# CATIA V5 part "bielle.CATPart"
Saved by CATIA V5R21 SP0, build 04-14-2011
Part number: bielle
Material "Laiton": density 8216 kg/m3, Young's modulus 1.31e+11 Pa, Poisson ratio 0.35, thermal expansion 1.67e-05 1/K
Bounding box of the stored display mesh (mm): x -4.5 to 4.5, y -3.5 to 3.5, z -20.75 to 20.75
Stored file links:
  C:\Users\Olivier\Desktop\redaction CATIA (local)\pompe à moteur de ventilation refait\bielle.CATPart
  C:\Program Files\Dassault Systemes\B21\win_b64\startup\materials\French\Catalog.CATMaterial
  C:\Users\Olivier\Desktop\redaction CATIA (local)\pompe à moteur de ventilation refait\Pompe_a_moteur_de_ventilation.CATProduct
  C:\Users\Olivier\Desktop\redaction CATIA (local)\pompe à moteur de ventilation refait\Ecrou a collerette M5.CATPart
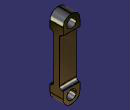
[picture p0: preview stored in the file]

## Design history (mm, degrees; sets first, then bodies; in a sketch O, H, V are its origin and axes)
Body1 (main body), material "Laiton"
  Sketch1 on yz-plane, origin (0, 0, 0), H (0, 1, 0), V (0, 0, 1)
    line L1 (3.5, 20.75) -> (3.5, 12.75)
    line L2 (3.5, -20.75) -> (-3.5, -20.75)
    line L3 (-3.5, -20.75) -> (-3.5, -12.75)
    line L4 (-3.5, 20.75) -> (3.5, 20.75)
    point P1 (3.5, 20.75)
    point P2 (3.5, -20.75)
    point P5 (3.5, 12.75)
    point P6 (-3.5, 12.75)
    point P7 (-3.5, -12.75)
    point P8 (3.5, -12.75)
    line L5 (1.5, 12.75) -> (1.5, -12.75)
    point P9 (1.5, 12.75)
    point P10 (1.5, -12.75)
    point P11 (-1.5, -12.75)
    point P12 (-1.5, 12.75)
    line L6 (-1.5, 12.75) -> (-1.5, -12.75)
    line L7 (3.5, -12.75) -> (3.5, -20.75)
    line L8 (-3.5, 12.75) -> (-3.5, 20.75)
    point P13 (1.5, 12.75)
    point P14 (-1.5, 12.75)
    point P15 (-1.5, -12.75)
    point P16 (1.5, -12.75)
    line L9 (3.5, 12.75) -> (1.5, 12.75)
    point P17 (1.5, 12.75)
    line L10 (-3.5, 12.75) -> (-1.5, 12.75)
    point P18 (-1.5, 12.75)
    line L11 (-3.5, -12.75) -> (-1.5, -12.75)
    point P19 (-1.5, -12.75)
    line L12 (3.5, -12.75) -> (1.5, -12.75)
    point P20 (1.5, -12.75)
    length L4 = 7
    distance L5 V = 1.5
    distance P1 P2 = 41.5
    length L1 = 8
    length L3 = 8
    vertical: L1 V, L3 V, L5 V, L7 V, L8 V
    horizontal: L2 H, L4 H, L9 H, L10 H, L11 H, L12 H
    equidistance: L1 L3 O, L2 L4 O
    coincidence: P6 L3, L1 L7, L3 L8, L5 P9, L6 P12, L6 P11, L5 P10, P14 P12, P13 P9, P17 L5, P18 L6, P12 P18, P11 P15, P16 P10, P19 L6, P20 L5, P11 P19
    symmetry: P6 P7 H, P5 P8 H, P10 P11 V, P9 P12 V, L5 L6 V
  Pad1: profile Sketch1, direction (1, 0, 0), length 4.5, mirrored extent
  Sketch2 on zx-plane, origin (0, 0, 0), H (-1, 0, 0), V (0, 0, 1)
    circle A1 centre (0, 16.5) radius 2.5
    point P1 (0, 16.5)
    circle A2 centre (0, -16.5) radius 2.5
    distance P1 H = 16.5
    coincidence: P1 V
    symmetry: A1 A2 H
  Pocket1: profile Sketch2, direction (0, -1, 0), length 4.5, mirrored extent
  Fillet1: radius 4.25, on edge [start face of Pad1 | face of Pad1 from Sketch1.L2]; edge [face of Pad1 from Sketch1.L2 | end face of Pad1]; edge [start face of Pad1 | face of Pad1 from Sketch1.L4]; edge [face of Pad1 from Sketch1.L4 | end face of Pad1]
  Fillet2: radius 1.5, on edge [face of Pad1 from Sketch1.L9 | face of Pad1 from Sketch1.L5]; edge [face of Pad1 from Sketch1.L5 | face of Pad1 from Sketch1.L12]; edge [face of Pad1 from Sketch1.L11 | face of Pad1 from Sketch1.L6]; edge [face of Pad1 from Sketch1.L6 | face of Pad1 from Sketch1.L10]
